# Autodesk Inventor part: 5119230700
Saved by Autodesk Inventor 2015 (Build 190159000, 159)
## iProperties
Created: 2020-07
Part Number: 5119230700
Checked By: TraceParts S.A.
Material: Generic
Catalog Web Link: www.traceparts.com
Document SubType Name: Modeling
Designer: TraceParts
Density: 1 g/cm^3
Appearance: Default
Company: TraceParts S.A.
Author: TraceParts
REFERENCE: 5119230700
DESIGN: HIT-1000 P 0,55KW (230/400V 50HZ) - 5119230700
SUPPLIER: Soler & Palau
TraceParts.PartNumber: 10-20122018-119595
TraceParts.PartTitle: HIB-P/HIT-P
TraceParts.InstanceId: 10-20122018-1195952BBBDLPN6AJ5BHVHRAWLNSGNW
TraceParts.PartStatus: Published
TraceParts.PartVersion: 1.0.2
TRACEPARTS: TRACEPARTS
TraceParts.PartLanguage: en
TraceParts.ClassPath: SOLER_PALAU:10-20122018-119595
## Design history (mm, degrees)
feature "5119230700"
body "Solid1"
